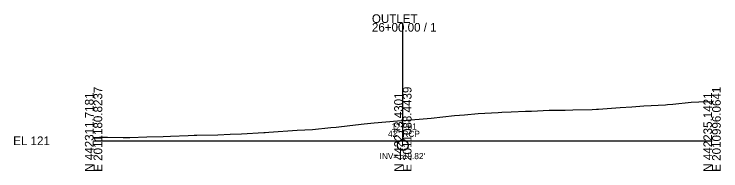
# Model space of a CAD drawing. Extents: x -26 to 1203, y -15 to 9526.
# Drawn here: x 974.3 to 1202.8, y 5990.3 to 6040.9 of the extents above; entities that cross this region are included whole.
import ezdxf

# ---------------------------------------------------------------- set-up
doc = ezdxf.new("R2010")
doc.units = 0
for name, color, linetype in [('Exist Cross Section Cell', 7, 'Continuous'), ('Exist XS Center Line Elevation Label', 7, 'Continuous'), ('Exist XS Ground Line', 7, 'Continuous'), ('Prop XSC Text', 7, 'Continuous')]:
    doc.layers.add(name, color=color, linetype=linetype)

msp = doc.modelspace()

# ---------------------------------------------------------------- linework, layer by layer
at = {"layer": 'Exist Cross Section Cell'}
for p, q in [((1100, 6000), (1100, 6038.04)), ((1000, 6000), (1100, 6000)), ((1100, 6000), (1200, 6000))]:
    msp.add_line(p, q, dxfattribs=at)
at = {"layer": 'Exist XS Ground Line'}
msp.add_lwpolyline([(1000, 6001.12), (1000.89, 6001.09), (1001.95, 6001.16), (1004.49, 6001.16), (1009.6, 6001.08), (1011.72, 6001.08), (1017.25, 6001.31), (1022.54, 6001.37), (1024.9, 6001.48), (1030.61, 6001.71), (1032.56, 6001.77), (1033.37, 6001.79), (1040.21, 6001.95), (1044.19, 6002.14), (1047.86, 6002.26), (1055.02, 6002.65), (1055.52, 6002.68), (1056.72, 6002.79), (1065.84, 6003.39), (1070.82, 6003.67), (1076.67, 6004.26), (1078.48, 6004.43), (1082.84, 6004.95), (1087.49, 6005.46), (1090.78, 6005.79), (1098.32, 6006.48), (1100, 6006.61), (1109.14, 6007.35), (1116.74, 6008.19), (1119.97, 6008.43), (1124.39, 6008.79), (1130.79, 6009.14), (1132.05, 6009.29), (1135.08, 6009.37), (1139.7, 6009.58), (1141.62, 6009.6), (1147.35, 6009.85), (1152.44, 6009.91), (1155.01, 6009.95), (1161.19, 6010.07), (1162.66, 6010.18), (1163.26, 6010.23), (1170.31, 6010.77), (1174.09, 6011), (1177.96, 6011.26), (1184.91, 6011.64), (1185.62, 6011.69), (1187.31, 6011.81), (1193.27, 6012.44), (1195.74, 6012.53), (1200, 6012.68)], dxfattribs=at)
at = {"layer": 'Prop XSC Text'}
msp.add_circle((1100, 5998.57), 1.75, dxfattribs=at)

# ---------------------------------------------------------------- texts
at = {"layer": 'Exist Cross Section Cell'}
for s, p in [('OUTLET', (1090, 6038.04)), ('26+00.00 / 1', (1090, 6035.24)), ('EL 121', (974, 5998.6))]:
    msp.add_text(s, height=2.8, dxfattribs=at).set_placement(p)
for s, p in [('E 2011180.8237', (1002.8, 5990)), ('E 2011088.4439', (1102.8, 5990)), ('E 2010996.0641', (1202.8, 5990)), ('N 442311.7181', (1000, 5990)), ('N 442273.4301', (1100, 5990)), ('N 442235.1421', (1200, 5990))]:
    msp.add_text(s, height=2.8, rotation=90, dxfattribs=at).set_placement(p)
at = {"layer": 'Exist XS Center Line Elevation Label'}
msp.add_text('127.61', height=2, dxfattribs=at).set_placement((1096.32, 6003.61))
at = {"layer": 'Prop XSC Text'}
for s, p in [('42" RCP', (1095.2, 6001.26)), ("INV=119.82'", (1092.49, 5994.08))]:
    msp.add_text(s, height=2, dxfattribs=at).set_placement(p)

doc.saveas('drawing.dxf')
